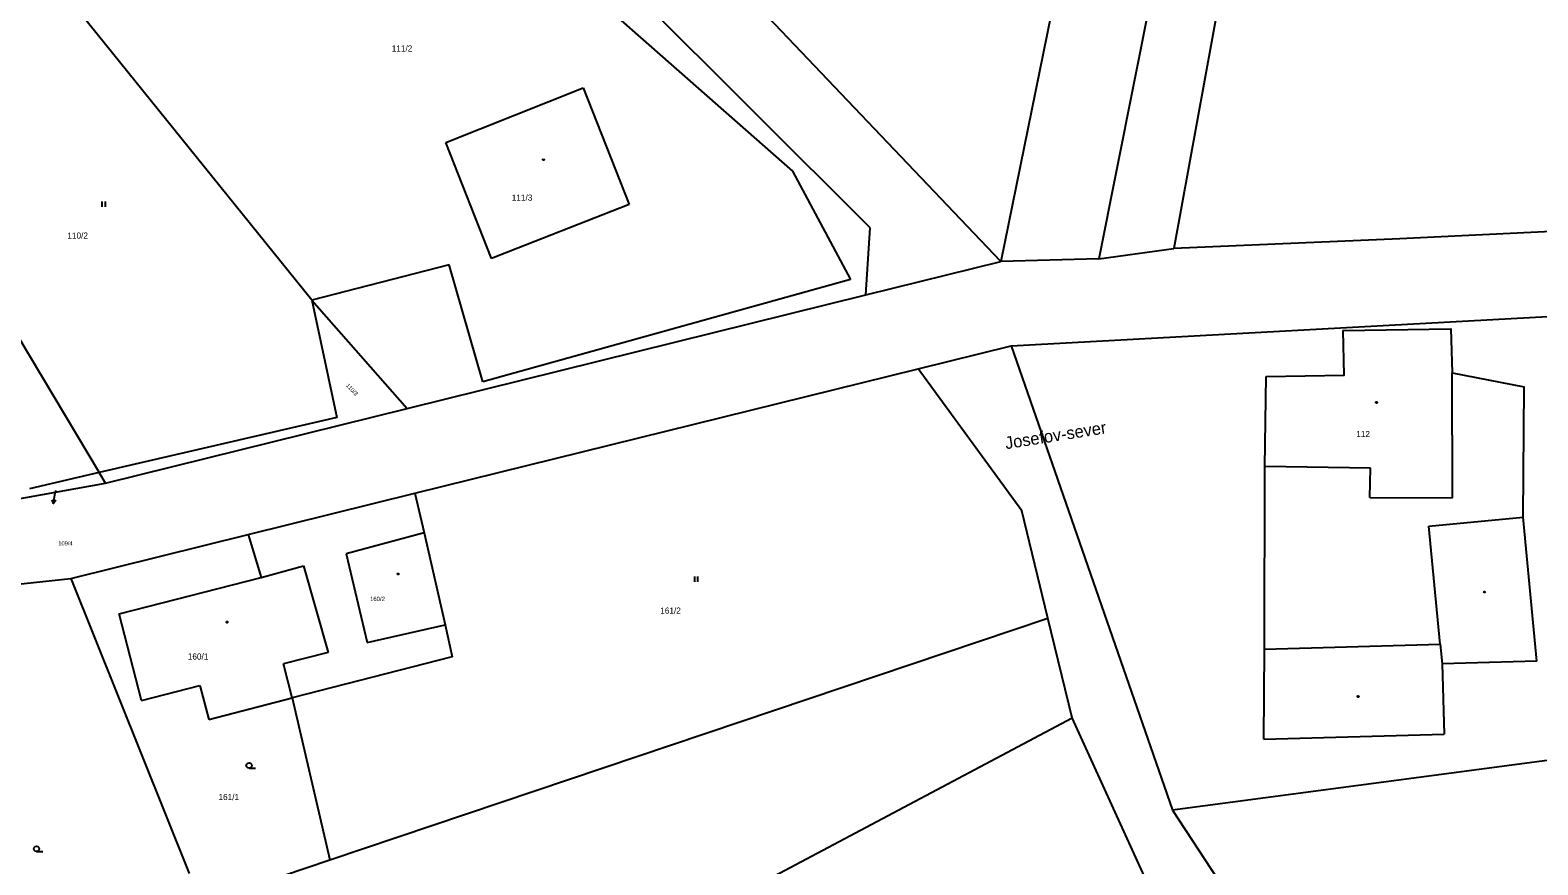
# Model space of a CAD drawing. Extents: x -871430 to -870620, y -1010094 to -1009649.
# Drawn here: x -870996.8 to -870892.6, y -1009857 to -1009799.4 of the extents above; entities that cross this region are included whole.
import ezdxf

# ---------------------------------------------------------------- set-up
doc = ezdxf.new("R2010")
doc.units = 0
for name, color, linetype in [('Vrstva 1', 7, 'Continuous'), ('Vrstva 2', 7, 'Continuous'), ('Vrstva 3', 7, 'Continuous'), ('Vrstva 4', 7, 'Continuous'), ('Vrstva 5', 7, 'Continuous'), ('Vrstva 7', 7, 'Continuous')]:
    doc.layers.add(name, color=color, linetype=linetype)

msp = doc.modelspace()

# ---------------------------------------------------------------- linework, layer by layer
at = {"layer": 'Vrstva 1'}
for p, q in [((-870909.18, -1009746.07), (-870922.93, -1009815.19)), ((-870910.58, -1009775.2), (-870917.75, -1009814.47)), ((-870970.06, -1009786.29), (-870944.09, -1009809.12)), ((-870924.55, -1009790.12), (-870929.69, -1009815.36)), ((-870929.69, -1009815.36), (-870950.56, -1009793.45)), ((-870977.29, -1009818.03), (-870995.93, -1009794.96)), ((-870938.72, -1009813.05), (-870956.49, -1009795.31)), ((-871010.06, -1009799.7), (-870991.98, -1009829.94)), ((-870968.03, -1009807.14), (-870958.55, -1009803.37)), ((-870958.55, -1009803.37), (-870955.38, -1009811.42)), ((-870964.87, -1009815.16), (-870968.03, -1009807.14)), ((-870944.09, -1009809.12), (-870940.07, -1009816.6)), ((-870955.38, -1009811.42), (-870964.87, -1009815.16)), ((-870874.68, -1009812.49), (-870902.13, -1009813.79)), ((-870939.01, -1009817.67), (-870938.72, -1009813.05)), ((-870922.93, -1009815.19), (-870917.75, -1009814.47)), ((-870902.13, -1009813.79), (-870917.75, -1009814.47)), ((-870967.8, -1009815.59), (-870977.29, -1009818.03)), ((-870965.47, -1009823.68), (-870967.8, -1009815.59)), ((-870939.01, -1009817.67), (-870929.69, -1009815.36)), ((-870922.93, -1009815.19), (-870929.69, -1009815.36)), ((-870940.07, -1009816.6), (-870965.47, -1009823.68)), ((-870970.7, -1009825.51), (-870939.01, -1009817.67)), ((-870977.29, -1009818.03), (-870975.56, -1009826.14)), ((-870977.29, -1009818.03), (-870970.7, -1009825.51)), ((-870928.98, -1009821.19), (-870869.82, -1009817.95)), ((-870935.4, -1009822.78), (-870928.98, -1009821.19)), ((-870928.98, -1009821.19), (-870917.84, -1009853.25)), ((-870970.17, -1009831.37), (-870935.4, -1009822.78)), ((-870928.24, -1009832.57), (-870935.4, -1009822.78)), ((-870911.46, -1009829.51), (-870911.36, -1009823.31)), ((-870898.52, -1009823.06), (-870893.55, -1009824.03)), ((-870893.6, -1009833.02), (-870893.55, -1009824.03)), ((-870991.55, -1009830.67), (-870970.7, -1009825.51)), ((-870975.56, -1009826.14), (-870991.98, -1009829.94)), ((-870991.98, -1009829.94), (-870996.8, -1009831.05)), ((-870991.55, -1009830.67), (-870991.98, -1009829.94)), ((-870911.48, -1009842.14), (-870911.46, -1009829.51)), ((-871007.23, -1009833.47), (-870991.55, -1009830.67)), ((-870981.69, -1009834.22), (-870970.17, -1009831.37)), ((-870970.17, -1009831.37), (-870969.54, -1009834.11)), ((-870926.44, -1009839.99), (-870928.24, -1009832.57)), ((-870892.66, -1009842.97), (-870893.6, -1009833.02)), ((-870993.95, -1009837.25), (-870981.69, -1009834.22)), ((-870981.69, -1009834.22), (-870980.8, -1009837.18)), ((-870969.54, -1009834.11), (-870974.91, -1009835.54)), ((-870969.54, -1009834.11), (-870968.09, -1009840.45)), ((-870974.91, -1009835.54), (-870973.47, -1009841.68)), ((-871009.01, -1009838.9), (-870993.95, -1009837.25)), ((-870993.95, -1009837.25), (-870985.77, -1009857.62)), ((-870990.6, -1009839.7), (-870980.8, -1009837.18)), ((-870989.06, -1009845.67), (-870990.6, -1009839.7)), ((-870976.04, -1009856.67), (-870926.44, -1009839.99)), ((-870973.47, -1009841.68), (-870968.09, -1009840.45)), ((-870968.09, -1009840.45), (-870967.59, -1009842.65)), ((-870924.77, -1009846.86), (-870926.44, -1009839.99)), ((-870967.59, -1009842.65), (-870978.66, -1009845.5)), ((-870911.52, -1009848.34), (-870911.48, -1009842.14)), ((-870892.66, -1009842.97), (-870899.21, -1009843.15)), ((-870899.21, -1009843.15), (-870899.07, -1009847.99)), ((-870989.06, -1009845.67), (-870985.02, -1009844.63)), ((-870985.02, -1009844.63), (-870984.41, -1009846.98)), ((-870984.41, -1009846.98), (-870978.66, -1009845.5)), ((-870978.66, -1009845.5), (-870976.04, -1009856.67)), ((-870950.59, -1009860.56), (-870924.77, -1009846.86)), ((-870918.22, -1009861.2), (-870924.77, -1009846.86)), ((-870885.13, -1009848.9), (-870917.84, -1009853.25)), ((-870911.52, -1009848.34), (-870899.07, -1009847.99)), ((-870917.84, -1009853.25), (-870905.75, -1009871.61)), ((-870984.48, -1009859.51), (-870976.04, -1009856.67))]:
    msp.add_line(p, q, dxfattribs=at)
msp.add_lwpolyline([(-870911.36, -1009823.31), (-870905.98, -1009823.21), (-870906.05, -1009820.13), (-870898.6, -1009820.01), (-870898.52, -1009823.06)], dxfattribs=at)
at = {"layer": 'Vrstva 3'}
for p, q in [((-870991.805, -1009811.215), (-870991.805, -1009811.59)), ((-870991.555, -1009811.59), (-870991.555, -1009811.215)), ((-870950.865, -1009837.105), (-870950.865, -1009837.48)), ((-870950.615, -1009837.48), (-870950.615, -1009837.105))]:
    msp.add_line(p, q, dxfattribs=at)
for points in [[(-870981.63, -1009850.35), (-870981.725, -1009850.325), (-870981.792, -1009850.255), (-870981.818, -1009850.162), (-870981.792, -1009850.07), (-870981.725, -1009850), (-870981.63, -1009849.975), (-870981.535, -1009850), (-870981.468, -1009850.07), (-870981.442, -1009850.162), (-870981.468, -1009850.255), (-870981.535, -1009850.325), (-870981.63, -1009850.35), (-870981.192, -1009850.35)], [(-870996.31, -1009856.11), (-870996.405, -1009856.085), (-870996.472, -1009856.015), (-870996.498, -1009855.922), (-870996.472, -1009855.83), (-870996.405, -1009855.76), (-870996.31, -1009855.735), (-870996.215, -1009855.76), (-870996.148, -1009855.83), (-870996.122, -1009855.922), (-870996.148, -1009856.015), (-870996.215, -1009856.085), (-870996.31, -1009856.11), (-870995.872, -1009856.11)]]:
    msp.add_lwpolyline(points, dxfattribs=at)
at = {"layer": 'Vrstva 4'}
for p, q in [((-870898.48, -1009831.69), (-870898.52, -1009823.06)), ((-870904.16, -1009829.63), (-870911.46, -1009829.51)), ((-870904.2, -1009831.65), (-870904.16, -1009829.63)), ((-870904.2, -1009831.65), (-870898.48, -1009831.69)), ((-870900.12, -1009833.64), (-870893.6, -1009833.02)), ((-870899.34, -1009841.79), (-870900.12, -1009833.64)), ((-870980.8, -1009837.18), (-870977.86, -1009836.38)), ((-870977.86, -1009836.38), (-870976.17, -1009842.36)), ((-870976.17, -1009842.36), (-870979.26, -1009843.15)), ((-870911.48, -1009842.14), (-870899.34, -1009841.79)), ((-870899.34, -1009841.79), (-870899.21, -1009843.15)), ((-870978.66, -1009845.5), (-870979.26, -1009843.15))]:
    msp.add_line(p, q, dxfattribs=at)
at = {"layer": 'Vrstva 5'}
for points in [[(-870961.29, -1009808.288), (-870961.265, -1009808.292), (-870961.253, -1009808.315), (-870961.248, -1009808.33), (-870961.253, -1009808.352), (-870961.273, -1009808.37), (-870961.29, -1009808.372), (-870961.312, -1009808.365), (-870961.328, -1009808.35), (-870961.332, -1009808.33), (-870961.328, -1009808.308), (-870961.308, -1009808.29), (-870961.29, -1009808.288)], [(-870903.74, -1009825.058), (-870903.715, -1009825.062), (-870903.702, -1009825.085), (-870903.698, -1009825.1), (-870903.702, -1009825.122), (-870903.722, -1009825.14), (-870903.74, -1009825.142), (-870903.762, -1009825.135), (-870903.778, -1009825.12), (-870903.782, -1009825.1), (-870903.778, -1009825.078), (-870903.758, -1009825.06), (-870903.74, -1009825.058)], [(-870971.33, -1009836.898), (-870971.305, -1009836.902), (-870971.292, -1009836.925), (-870971.288, -1009836.94), (-870971.292, -1009836.962), (-870971.312, -1009836.98), (-870971.33, -1009836.982), (-870971.352, -1009836.975), (-870971.367, -1009836.96), (-870971.372, -1009836.94), (-870971.367, -1009836.918), (-870971.347, -1009836.9), (-870971.33, -1009836.898)], [(-870896.258, -1009838.143), (-870896.235, -1009838.18), (-870896.258, -1009838.218), (-870896.302, -1009838.218), (-870896.325, -1009838.18), (-870896.302, -1009838.143), (-870896.258, -1009838.143)], [(-870983.15, -1009840.228), (-870983.125, -1009840.232), (-870983.112, -1009840.255), (-870983.108, -1009840.27), (-870983.112, -1009840.292), (-870983.133, -1009840.31), (-870983.15, -1009840.312), (-870983.172, -1009840.305), (-870983.188, -1009840.29), (-870983.192, -1009840.27), (-870983.188, -1009840.248), (-870983.168, -1009840.23), (-870983.15, -1009840.228)], [(-870904.978, -1009845.362), (-870904.955, -1009845.4), (-870904.978, -1009845.438), (-870905.022, -1009845.438), (-870905.045, -1009845.4), (-870905.022, -1009845.362), (-870904.978, -1009845.362)]]:
    msp.add_lwpolyline(points, dxfattribs=at)
at = {"layer": 'Vrstva 7'}
for p in [(-870995.01, -1009831.17), (-870995.132, -1009832.083)]:
    msp.add_line(p, (-870995.03, -1009831.34), dxfattribs=at)
msp.add_lwpolyline([(-870994.974, -1009831.852), (-870995.132, -1009832.083), (-870995.222, -1009831.818)], dxfattribs=at)

# ---------------------------------------------------------------- texts
at = {"layer": 'Vrstva 2'}
for s, height, p in [('111/2', 0.425, (-870971.772, -1009800.87)), ('111/3', 0.425, (-870963.482, -1009811.17)), ('110/2', 0.425, (-870994.182, -1009813.79)), ('112', 0.425, (-870905.142, -1009827.49)), ('109/4', 0.025, (-870995.414, -1009831.03)), ('160/2', 0.2975, (-870973.271, -1009838.81)), ('161/2', 0.425, (-870953.222, -1009839.68)), ('160/1', 0.425, (-870985.862, -1009842.85)), ('161/1', 0.425, (-870983.742, -1009852.55))]:
    msp.add_text(s, height=height, dxfattribs=at).set_placement(p)
msp.add_text('110/3', height=0.285, rotation=312.94955, dxfattribs=at).set_placement((-870974.962, -1009823.942))
at = {"layer": 'Vrstva 7'}
msp.add_text('Josefov-sever', height=0.85, rotation=8.99544, dxfattribs=at).set_placement((-870929.34, -1009828.33))
msp.add_text('109/4', height=0.285, dxfattribs=at).set_placement((-870994.805, -1009834.965))

doc.saveas('drawing.dxf')
